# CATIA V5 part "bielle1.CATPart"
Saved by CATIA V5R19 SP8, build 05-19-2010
Part number: bielle1
Bounding box of the stored display mesh (mm): x -4.48 to 49.48, y -23 to 23, z -4.48 to 36.48
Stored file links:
  G:\EU_thinkMotion\CFAO_2010\MMS_groupe1\MMS_groupe1\A reprendre\OK\glenerrant\glenerrant\glenerrant\bielle1.CATPart
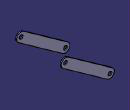
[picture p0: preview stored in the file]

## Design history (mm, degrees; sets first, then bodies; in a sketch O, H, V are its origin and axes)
Set1
  Point1: (0, 0, 0)
  Point2: (45, 0, 32)
  Plane1: type Offset, RefPlane zx-plane, Offset 22
Body1 (main body)
  Plane2: stored without definition
  Sketch1 on Plane1, origin (0, 22, 0), H (-1, 0, 0), V (0, 0, 1)
    arc A1 centre (-45, 32) radius 4.5 from (-42.3921, 35.6673) to (-47.6079, 28.3327) ccw
    point P1 (-45, 32)
    circle A2 centre (0, 0) radius 2
    point P2 (0, 0)
    circle A3 centre (-45, 32) radius 2
    point P3 (-45, 32)
    arc A4 centre (0, 0) radius 4.5 from (-2.6079, -3.6673) to (2.6079, 3.6673) ccw
    point P4 (0, 0)
    reference projected point E1 (0, 0) from Point1
    reference projected point E2 (-45, 32) from Point2
    reference projected point E3 (0, 0) from Point1
    reference projected point E4 (-45, 32) from Point2
    line L1 (-42.3921, 35.6673) -> (2.6079, 3.6673)
    line L2 (-47.6079, 28.3327) -> (-2.6079, -3.6673)
    radius A1 = 4.5
    radius A4 = 4.5
    radius A2 = 2
    radius A3 = 2
    coincidence: P2 E1, P3 E2, P4 E3, E4 P1
    parallelism: L2 L1
    tangency: L1 A4, L2 A4, A1 L1
  Pad1: profile Sketch1, direction (0, 1, 0), length 1
  Point3 to Point6: stored without definition
  Sketch2 on Plane2, origin (0, -22, 0), H (-1, 0, 0), V (0, 0, 1)
    circle A1 centre (-45, 32) radius 2
    point P1 (-45, 32)
    arc A2 centre (-45, 32) radius 4.5 from (-42.3921, 35.6673) to (-47.6079, 28.3327) ccw
    point P2 (-45, 32)
    circle A3 centre (0, 0) radius 2
    point P3 (0, 0)
    arc A4 centre (0, 0) radius 4.5 from (-2.6079, -3.6673) to (2.6079, 3.6673) ccw
    point P4 (0, 0)
    reference projected point E1 (-45, 32) from Point3
    reference projected point E2 (0, 0) from Point4
    reference projected point E3 (-45, 32) from Point5
    reference projected point E4 (0, 0) from Point6
    line L1 (2.6079, 3.6673) -> (-42.3921, 35.6673)
    point P7 (-47.6079, 28.3327)
    point P8 (-2.6079, -3.6673)
    line L2 (-47.6079, 28.3327) -> (-2.6079, -3.6673)
    point P9 (-47.6079, 28.3327)
    point P10 (-2.6079, -3.6673)
    radius A2 = 4.5
    radius A4 = 4.5
    radius A1 = 2
    radius A3 = 2
    coincidence: P1 E1, P3 E2, P2 E3, P4 E4, P9 A2, P10 A4, P7 P9, P8 P10
    tangency: L1 A2, A4 L2, L2 A2
    parallelism: L2 L1
  Pad2: profile Sketch2, direction (0, -1, 0), length 1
